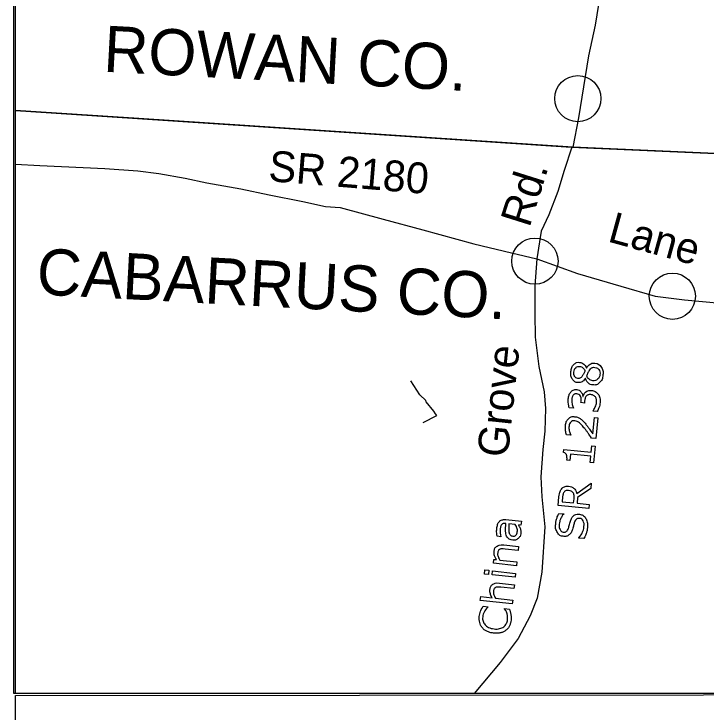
# Model space of a CAD drawing. Extents: x 1530800 to 1534168, y 642962 to 645162.
# Drawn here: x 1531284.6 to 1531509.4, y 644498.9 to 644725.7 of the extents above; entities that cross this region are included whole.
import ezdxf

# ---------------------------------------------------------------- set-up
doc = ezdxf.new("R2010")
doc.units = 0
for name, color, linetype in [('Old_Level_1', 7, 'Continuous'), ('Old_Level_11', 7, 'Continuous'), ('Old_Level_19', 7, 'Continuous'), ('Old_Level_29', 7, 'Continuous'), ('Old_Level_32', 7, 'Continuous'), ('Old_Level_49', 7, 'Continuous'), ('Old_Level_52', 7, 'Continuous'), ('Old_Level_62', 7, 'Continuous')]:
    doc.layers.add(name, color=color, linetype=linetype)

msp = doc.modelspace()

# ---------------------------------------------------------------- linework, layer by layer
at = {"layer": 'Old_Level_1'}
for centre in [(1531467.72, 644698.18), (1531453.8, 644645.38), (1531498.43, 644633.97)]:
    msp.add_circle(centre, 7.5, dxfattribs=at)
at = {"layer": 'Old_Level_11'}
for points in [[(1531470.52, 644610.58), (1531470.56, 644610.58)], [(1531470.18, 644607.28), (1531470.14, 644607.28)], [(1531469.36, 644601.44), (1531469.46, 644601.43)], [(1531469.9, 644599.89), (1531469.84, 644599.29), (1531468.73, 644599.4), (1531468.78, 644599.87)], [(1531466.35, 644597.67), (1531466.35, 644597.61), (1531464.95, 644597.75)], [(1531474.04, 644596.54), (1531472.65, 644596.68), (1531472.66, 644596.78)], [(1531474.25, 644594.5), (1531473.58, 644587.76), (1531472.17, 644587.9)], [(1531472.56, 644589.26), (1531473.1, 644594.62), (1531474.25, 644594.5)], [(1531465.47, 644588.89), (1531465.46, 644588.83), (1531464.06, 644588.97)], [(1531463.03, 644583.18), (1531463.13, 644584.21), (1531472.1, 644583.31), (1531472.31, 644585.34), (1531473.32, 644585.24)], [(1531473.32, 644585.24), (1531472.78, 644579.85), (1531471.76, 644579.95), (1531471.97, 644582.02), (1531465.3, 644582.7), (1531465.09, 644580.62), (1531464.19, 644580.72)], [(1531472.11, 644573.24), (1531471.94, 644571.52), (1531467.65, 644568.59), (1531467.46, 644566.73), (1531471.42, 644566.33), (1531471.28, 644565), (1531461.33, 644566.01), (1531461.61, 644568.79)], [(1531467.39, 644569.93), (1531472.11, 644573.24)], [(1531462.77, 644568.78), (1531462.61, 644567.21), (1531466.36, 644566.84), (1531466.49, 644568.18)], [(1531461.59, 644563.43), (1531463.16, 644563.27), (1531463.15, 644563.18)], [(1531444.34, 644560.13), (1531444.14, 644560.16)], [(1531444.34, 644561.41), (1531449.4, 644560.85)], [(1531447.43, 644559.79), (1531445.35, 644560.02)], [(1531449.4, 644560.85), (1531449.26, 644559.59), (1531448.47, 644559.68)], [(1531442.76, 644555.91), (1531442.75, 644555.84), (1531441.48, 644555.98)], [(1531469.68, 644555.26), (1531468.02, 644555.43), (1531468.03, 644555.52)], [(1531443.65, 644553.17), (1531448.49, 644552.64)], [(1531448.49, 644552.64), (1531448.35, 644551.38), (1531444.1, 644551.85)], [(1531442.37, 644548.28), (1531447.94, 644547.66), (1531447.8, 644546.4), (1531440.34, 644547.23), (1531440.48, 644548.49), (1531441.31, 644548.4)], [(1531438.83, 644544.98), (1531438.67, 644543.56), (1531437.37, 644543.7), (1531437.53, 644545.12), (1531438.83, 644544.98)], [(1531447.53, 644543.93), (1531447.39, 644542.67), (1531439.93, 644543.5), (1531440.07, 644544.76), (1531447.53, 644543.93)], [(1531442.28, 644540.77), (1531447.12, 644540.24)], [(1531447.12, 644540.24), (1531446.98, 644538.98), (1531442.73, 644539.45)], [(1531440.99, 644535.88), (1531446.57, 644535.26), (1531446.43, 644534.01), (1531436.04, 644535.16), (1531436.18, 644536.41), (1531439.93, 644536)], [(1531436.99, 644533.26), (1531438.56, 644533.09), (1531438.54, 644532.99)], [(1531443.95, 644532.4), (1531443.96, 644532.49), (1531445.51, 644532.32)]]:
    msp.add_lwpolyline(points, dxfattribs=at)
for points in [[(1531470.14, 644607.28), (1531469.63, 644606.52), (1531469.08, 644606.19), (1531468.53, 644605.85), (1531467.77, 644605.93), (1531466.65, 644606.04), (1531465.99, 644607.04), (1531465.34, 644608.04), (1531465.48, 644609.46), (1531465.63, 644610.95), (1531466.44, 644611.77), (1531467.24, 644612.59), (1531468.34, 644612.48), (1531469.02, 644612.41), (1531469.63, 644611.92), (1531470.24, 644611.43), (1531470.52, 644610.58)], [(1531473.24, 644612.25), (1531474.53, 644612.12), (1531475.29, 644611.03), (1531476.04, 644609.94), (1531475.89, 644608.41), (1531475.72, 644606.8), (1531474.79, 644605.92), (1531473.86, 644605.04), (1531472.56, 644605.18), (1531471.73, 644605.26), (1531471.1, 644605.81), (1531470.48, 644606.36), (1531470.18, 644607.28)], [(1531470.56, 644610.58), (1531471.06, 644611.47), (1531471.7, 644611.91), (1531472.33, 644612.34), (1531473.24, 644612.25)], [(1531468.23, 644611.16), (1531467.51, 644611.23), (1531467.03, 644610.72), (1531466.55, 644610.21), (1531466.46, 644609.36), (1531466.38, 644608.51), (1531466.73, 644607.93), (1531467.07, 644607.35), (1531467.75, 644607.28), (1531468.23, 644607.24), (1531468.61, 644607.47), (1531468.99, 644607.71), (1531469.32, 644608.23), (1531469.47, 644608.46), (1531469.71, 644608.91), (1531469.95, 644609.35), (1531470.12, 644609.78), (1531469.74, 644610.49), (1531469.3, 644610.79), (1531468.85, 644611.1), (1531468.23, 644611.16)], [(1531473.23, 644610.87), (1531472.62, 644610.93), (1531472.22, 644610.7), (1531471.82, 644610.46), (1531471.37, 644609.71), (1531471.19, 644609.41), (1531471.02, 644609.05), (1531470.86, 644608.69), (1531470.57, 644608.09), (1531470.83, 644607.45), (1531471.36, 644607.03), (1531471.88, 644606.61), (1531472.59, 644606.54), (1531473.49, 644606.45), (1531474.14, 644607.01), (1531474.79, 644607.58), (1531474.89, 644608.53), (1531474.99, 644609.51), (1531474.55, 644610.14), (1531474.1, 644610.78), (1531473.23, 644610.87)], [(1531464.95, 644597.75), (1531464.77, 644598.24), (1531464.65, 644599.06), (1531464.53, 644599.87), (1531464.61, 644600.61), (1531464.68, 644601.34), (1531464.87, 644601.88), (1531465.06, 644602.42), (1531465.4, 644602.84), (1531465.77, 644603.29), (1531466.25, 644603.49), (1531466.73, 644603.7), (1531467.34, 644603.63), (1531468.16, 644603.55), (1531468.72, 644602.9), (1531469.28, 644602.25), (1531469.36, 644601.44)], [(1531470.25, 644602.8), (1531470.57, 644603.1), (1531471.03, 644603.26), (1531471.48, 644603.42), (1531472.17, 644603.35), (1531472.85, 644603.28), (1531473.4, 644602.98), (1531473.94, 644602.67), (1531474.32, 644602.18), (1531474.73, 644601.64), (1531474.89, 644600.94), (1531475.05, 644600.23), (1531474.96, 644599.43), (1531474.88, 644598.6), (1531474.6, 644597.82), (1531474.33, 644597.03), (1531474.04, 644596.54)], [(1531468.78, 644599.87), (1531468.88, 644600.88), (1531468.52, 644601.53), (1531468.16, 644602.18), (1531467.34, 644602.26), (1531466.98, 644602.3), (1531466.69, 644602.17), (1531466.4, 644602.05), (1531466.2, 644601.79), (1531466, 644601.52), (1531465.9, 644601.2), (1531465.8, 644600.88), (1531465.76, 644600.46), (1531465.69, 644599.83), (1531465.85, 644599.09), (1531466, 644598.35), (1531466.35, 644597.67)], [(1531469.46, 644601.43), (1531469.54, 644601.75), (1531469.76, 644602.14), (1531469.97, 644602.54), (1531470.25, 644602.8)], [(1531472.66, 644596.78), (1531473.09, 644597.31), (1531473.41, 644598.06), (1531473.74, 644598.8), (1531473.81, 644599.52), (1531473.85, 644599.94), (1531473.76, 644600.43), (1531473.67, 644600.92), (1531473.42, 644601.24), (1531473.16, 644601.58), (1531472.82, 644601.77), (1531472.48, 644601.95), (1531471.93, 644602.01), (1531471.4, 644602.06), (1531471.03, 644601.92), (1531470.66, 644601.79), (1531470.43, 644601.51), (1531470.19, 644601.23), (1531470.07, 644600.81), (1531469.95, 644600.39), (1531469.9, 644599.89)], [(1531464.06, 644588.97), (1531463.87, 644589.47), (1531463.76, 644590.28), (1531463.65, 644591.09), (1531463.72, 644591.83), (1531463.88, 644593.36), (1531464.7, 644594.16), (1531465.53, 644594.96), (1531466.79, 644594.83), (1531467.36, 644594.77), (1531467.83, 644594.58), (1531468.31, 644594.38), (1531468.72, 644594.06), (1531469.11, 644593.76), (1531469.47, 644593.37), (1531469.84, 644592.97), (1531470.28, 644592.42), (1531470.91, 644591.64), (1531471.49, 644590.81), (1531472.07, 644589.98), (1531472.56, 644589.26)], [(1531472.17, 644587.9), (1531471.64, 644588.67), (1531471.11, 644589.43), (1531470.58, 644590.2), (1531470.05, 644590.87), (1531468.93, 644592.28), (1531468.25, 644592.83), (1531467.57, 644593.38), (1531466.72, 644593.47), (1531465.94, 644593.54), (1531465.45, 644593.08), (1531464.96, 644592.61), (1531464.87, 644591.69), (1531464.81, 644591.08), (1531464.95, 644590.35), (1531465.1, 644589.61), (1531465.47, 644588.89)], [(1531464.19, 644580.72), (1531464.23, 644581.14), (1531464.21, 644581.63), (1531464.18, 644582.11), (1531464.08, 644582.37), (1531463.94, 644582.7), (1531463.7, 644582.9), (1531463.46, 644583.1), (1531463.03, 644583.18)], [(1531461.61, 644568.79), (1531461.7, 644569.69), (1531461.88, 644570.28), (1531462.06, 644570.87), (1531462.41, 644571.32), (1531462.8, 644571.83), (1531463.35, 644572.08), (1531463.9, 644572.34), (1531464.7, 644572.26), (1531465.77, 644572.15), (1531466.44, 644571.53), (1531467.11, 644570.92), (1531467.39, 644569.93)], [(1531464.66, 644570.87), (1531464.23, 644570.92), (1531463.88, 644570.8), (1531463.54, 644570.68), (1531463.28, 644570.36), (1531463.06, 644570.09), (1531462.94, 644569.7), (1531462.82, 644569.31), (1531462.77, 644568.78)], [(1531466.49, 644568.18), (1531466.55, 644568.81), (1531466.49, 644569.29), (1531466.43, 644569.77), (1531466.16, 644570.13), (1531465.91, 644570.46), (1531465.56, 644570.64), (1531465.22, 644570.82), (1531464.66, 644570.87)], [(1531468.03, 644555.52), (1531468.73, 644556.22), (1531469.17, 644557.17), (1531469.61, 644558.13), (1531469.7, 644559), (1531469.82, 644560.23), (1531469.43, 644560.96), (1531469.04, 644561.69), (1531468.28, 644561.77), (1531467.61, 644561.84), (1531467.27, 644561.54), (1531466.92, 644561.25), (1531466.68, 644560.61), (1531466.5, 644560.12), (1531466.35, 644559.54), (1531466.2, 644558.96), (1531466.01, 644558.32), (1531465.59, 644557.02), (1531464.85, 644556.45), (1531464.11, 644555.88), (1531463.02, 644555.99), (1531461.77, 644556.12), (1531461.08, 644557.25), (1531460.38, 644558.39), (1531460.55, 644560.02), (1531460.65, 644561.07), (1531460.94, 644561.93), (1531461.23, 644562.78), (1531461.59, 644563.43)], [(1531463.15, 644563.18), (1531462.61, 644562.66), (1531462.2, 644561.76), (1531461.79, 644560.86), (1531461.69, 644559.89), (1531461.59, 644558.83), (1531461.96, 644558.14), (1531462.34, 644557.45), (1531463.03, 644557.38), (1531463.65, 644557.31), (1531464.04, 644557.6), (1531464.42, 644557.88), (1531464.69, 644558.68), (1531464.83, 644559.1), (1531465.04, 644559.87), (1531465.25, 644560.65), (1531465.45, 644561.18), (1531465.86, 644562.26), (1531466.51, 644562.77), (1531467.16, 644563.27), (1531468.23, 644563.16)], [(1531468.23, 644563.16), (1531468.81, 644563.1), (1531469.35, 644562.78), (1531469.89, 644562.45), (1531470.23, 644561.92), (1531470.61, 644561.34), (1531470.78, 644560.61), (1531470.95, 644559.87), (1531470.84, 644558.87), (1531470.74, 644557.79), (1531470.45, 644556.95), (1531470.16, 644556.11), (1531469.68, 644555.26)], [(1531441.48, 644555.98), (1531441.42, 644556.36), (1531441.37, 644557.07), (1531441.33, 644557.78), (1531441.41, 644558.45), (1531441.49, 644559.24), (1531441.69, 644559.81), (1531441.88, 644560.38), (1531442.24, 644560.77), (1531442.6, 644561.15), (1531443.11, 644561.32), (1531443.62, 644561.49), (1531444.34, 644561.41)], [(1531444.14, 644560.16), (1531443.72, 644560.2), (1531443.42, 644560.08), (1531443.12, 644559.97), (1531442.93, 644559.7), (1531442.75, 644559.45), (1531442.66, 644559.09), (1531442.56, 644558.72), (1531442.52, 644558.31), (1531442.46, 644557.82), (1531442.52, 644557.2), (1531442.59, 644556.58), (1531442.76, 644555.91)], [(1531448.47, 644559.68), (1531448.57, 644559.5), (1531448.74, 644559.19), (1531448.91, 644558.89), (1531449, 644558.61), (1531449.12, 644558.28), (1531449.18, 644557.86), (1531449.24, 644557.44), (1531449.18, 644556.9), (1531449.07, 644555.89), (1531448.32, 644555.27), (1531447.57, 644554.64), (1531446.54, 644554.76), (1531445.69, 644554.85), (1531445.21, 644555.27), (1531444.72, 644555.69), (1531444.5, 644556.4), (1531444.27, 644557.11), (1531444.27, 644558.07), (1531444.27, 644559.04), (1531444.34, 644560.13)], [(1531445.35, 644560.02), (1531445.32, 644559.45), (1531445.3, 644558.67), (1531445.28, 644557.88), (1531445.36, 644557.42), (1531445.45, 644556.86), (1531445.74, 644556.5), (1531446.03, 644556.13), (1531446.6, 644556.06), (1531447.24, 644555.99), (1531447.61, 644556.34), (1531447.98, 644556.69), (1531448.07, 644557.48), (1531448.14, 644558.14), (1531447.94, 644558.71), (1531447.74, 644559.29), (1531447.43, 644559.79)], [(1531441.31, 644548.4), (1531440.89, 644549.04), (1531440.68, 644549.69), (1531440.48, 644550.35), (1531440.55, 644551.01), (1531440.68, 644552.22), (1531441.48, 644552.77), (1531442.28, 644553.32), (1531443.65, 644553.17)], [(1531444.1, 644551.85), (1531443.59, 644551.91), (1531443.13, 644551.9), (1531442.67, 644551.89), (1531442.4, 644551.75), (1531442.1, 644551.62), (1531441.93, 644551.32), (1531441.76, 644551.02), (1531441.7, 644550.52), (1531441.65, 644550.01), (1531441.84, 644549.42), (1531442.03, 644548.84), (1531442.37, 644548.28)], [(1531439.93, 644536), (1531439.51, 644536.64), (1531439.31, 644537.3), (1531439.1, 644537.95), (1531439.18, 644538.61), (1531439.31, 644539.82), (1531440.11, 644540.37), (1531440.91, 644540.93), (1531442.28, 644540.77)], [(1531442.73, 644539.45), (1531442.21, 644539.51), (1531441.76, 644539.5), (1531441.3, 644539.49), (1531441.03, 644539.36), (1531440.73, 644539.22), (1531440.56, 644538.92), (1531440.38, 644538.63), (1531440.33, 644538.13), (1531440.27, 644537.61), (1531440.46, 644537.03), (1531440.66, 644536.44), (1531440.99, 644535.88)], [(1531445.51, 644532.32), (1531445.63, 644531.93), (1531445.74, 644531.62), (1531445.84, 644531.31), (1531445.94, 644530.81), (1531446.02, 644530.39), (1531446.06, 644529.9), (1531446.1, 644529.41), (1531446.04, 644528.84), (1531445.92, 644527.76), (1531445.51, 644526.91), (1531445.11, 644526.06), (1531444.39, 644525.48), (1531443.69, 644524.9), (1531442.67, 644524.65), (1531441.65, 644524.4), (1531440.36, 644524.54), (1531439.13, 644524.68), (1531438.2, 644525.13), (1531437.27, 644525.59), (1531436.68, 644526.32), (1531436.1, 644527.02), (1531435.86, 644527.96), (1531435.62, 644528.89), (1531435.74, 644529.99), (1531435.83, 644530.79), (1531436.11, 644531.57), (1531436.39, 644532.34), (1531436.99, 644533.26)], [(1531438.54, 644532.99), (1531437.77, 644532.24), (1531437.36, 644531.47), (1531436.96, 644530.7), (1531436.86, 644529.77), (1531436.77, 644529.02), (1531436.95, 644528.39), (1531437.13, 644527.76), (1531437.59, 644527.23), (1531438.04, 644526.71), (1531438.77, 644526.37), (1531439.51, 644526.03), (1531440.51, 644525.92), (1531441.56, 644525.8), (1531442.34, 644526), (1531443.13, 644526.2), (1531443.65, 644526.59), (1531444.19, 644527.01), (1531444.5, 644527.61), (1531444.81, 644528.2), (1531444.88, 644528.9), (1531444.99, 644529.85), (1531444.76, 644530.72), (1531444.52, 644531.6), (1531443.95, 644532.4)]]:
    msp.add_open_spline(points, degree=3, dxfattribs=at)
at = {"layer": 'Old_Level_29'}
msp.add_line((1531284.62, 644504.86), (1531284.62, 644504.86), dxfattribs=at)
for points in [[(1531284.62, 644504.86), (1531284.62, 645044.6)], [(1531954.88, 644504.86), (1531284.62, 644504.86)]]:
    msp.add_lwpolyline(points, dxfattribs=at)
for points in [[(1531285.1, 645044.6), (1531955.36, 645044.6), (1531955.36, 644504.86), (1531285.1, 644504.86)], [(1531285.1, 644504.21), (1531955.36, 644504.86), (1531955.44, 644422.92), (1531285.18, 644422.27)]]:
    msp.add_lwpolyline(points, close=True, dxfattribs=at)
at = {"layer": 'Old_Level_32'}
for points in [[(1531501.63, 644818.33), (1531498.16, 644807.78), (1531492.38, 644793.64), (1531488.37, 644782.26), (1531485.36, 644775.9), (1531481.11, 644762.73), (1531480.71, 644761.51), (1531477.26, 644743.17), (1531474.89, 644731.57), (1531473.4, 644722.08), (1531471.15, 644712.04), (1531467.98, 644691.9), (1531466.1, 644682.38)], [(1531465.83, 644682.39), (1531463.25, 644674.78), (1531461.19, 644667.96), (1531458.31, 644660.43), (1531455.83, 644655.07), (1531454.41, 644646.09)], [(1531285.1, 644676.93), (1531292.97, 644676.4), (1531314.13, 644675.44), (1531324.79, 644674.7), (1531331.65, 644673.83), (1531340.25, 644672.3), (1531347.27, 644670.83), (1531358.29, 644668.88), (1531367.47, 644666.92), (1531378.37, 644664.72), (1531385.8, 644663.14), (1531390.55, 644662.77), (1531404.55, 644658.99), (1531417.41, 644655.56), (1531433.95, 644651.02), (1531446.19, 644648.13), (1531454.41, 644646.09)], [(1531454.41, 644646.09), (1531453.8, 644637.31), (1531453.8, 644628.21), (1531453.88, 644620.66), (1531455.1, 644611.15), (1531456.8, 644602.93), (1531457.23, 644597.54), (1531456.96, 644590.13), (1531456.36, 644584.19), (1531455.75, 644575.3), (1531455.99, 644568.84), (1531456.96, 644559.09), (1531456, 644544.38), (1531454.49, 644535.89), (1531452.21, 644530.14), (1531448.35, 644522.83), (1531442.5, 644515.03), (1531434.03, 644504.86)], [(1531454.41, 644646.09), (1531467.57, 644641.36), (1531481.68, 644637.23), (1531492.88, 644634.03), (1531502.42, 644632.85), (1531514.02, 644631.77), (1531523.24, 644630.23), (1531533.86, 644629.78), (1531544.2, 644627.84), (1531559.04, 644625.83), (1531573.76, 644624.43), (1531585.86, 644623.09), (1531591.22, 644622.24), (1531604.18, 644619.88), (1531613.6, 644618.44)]]:
    msp.add_lwpolyline(points, dxfattribs=at)
at = {"layer": 'Old_Level_49'}
msp.add_lwpolyline([(1531285.1, 644694.34), (1531324.69, 644691.72), (1531465.61, 644682.42), (1531588.73, 644677.01)], dxfattribs=at)
at = {"layer": 'Old_Level_52'}
msp.add_lwpolyline([(1531954.91, 644663.36), (1531779.67, 644668.88), (1531597.73, 644676.59), (1531466.06, 644682.38), (1531325.14, 644691.67), (1531285.1, 644694.33)], dxfattribs=at)
at = {"layer": 'Old_Level_62'}
msp.add_lwpolyline([(1531417.52, 644592.93), (1531421.92, 644595.2), (1531421.56, 644595.72), (1531420.96, 644596.6), (1531418.5, 644599.63), (1531418.39, 644600.14), (1531416.4, 644601.93), (1531413.46, 644606.5)], dxfattribs=at)

# ---------------------------------------------------------------- texts
at = {"layer": 'Old_Level_11'}
for s, rotation, p in [('SR 2180', 355.3306, (1531367.05, 644671.41)), ('Rd.', 72.5034, (1531452, 644656.02)), ('Lane', 344.6255, (1531477.07, 644651.85)), ('Grove', 83.9079, (1531444.96, 644581.36))]:
    msp.add_text(s, height=10, rotation=rotation, dxfattribs=at).set_placement(p)
at = {"layer": 'Old_Level_19'}
for s, p in [('ROWAN CO.', (1531313.44, 644706.95)), ('CABARRUS CO.', (1531291.72, 644634.61))]:
    msp.add_text(s, height=15, rotation=356.9394, dxfattribs=at).set_placement(p)

doc.saveas('drawing.dxf')
